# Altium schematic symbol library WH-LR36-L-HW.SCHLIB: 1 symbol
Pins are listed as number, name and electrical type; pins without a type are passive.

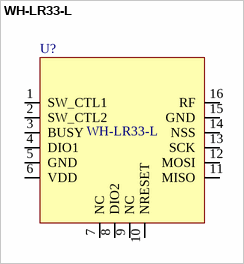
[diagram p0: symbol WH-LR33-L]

## WH-LR33-L
designator U?
footprint WH-LR33-L_Lib_V1.1 (WH-L101封装)
footprint WH-LR33-L_Lib_V1.1 (WH-L101封装)
pins: 1 SW_CTL1, 2 SW_CTL2, 3 BUSY, 4 DIO1, 5 GND, 6 VDD, 7 NC, 8 DIO2, 9 NC, 10 NRESET, 11 MISO, 12 MOSI, 13 SCK, 14 NSS, 15 GND, 16 RF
